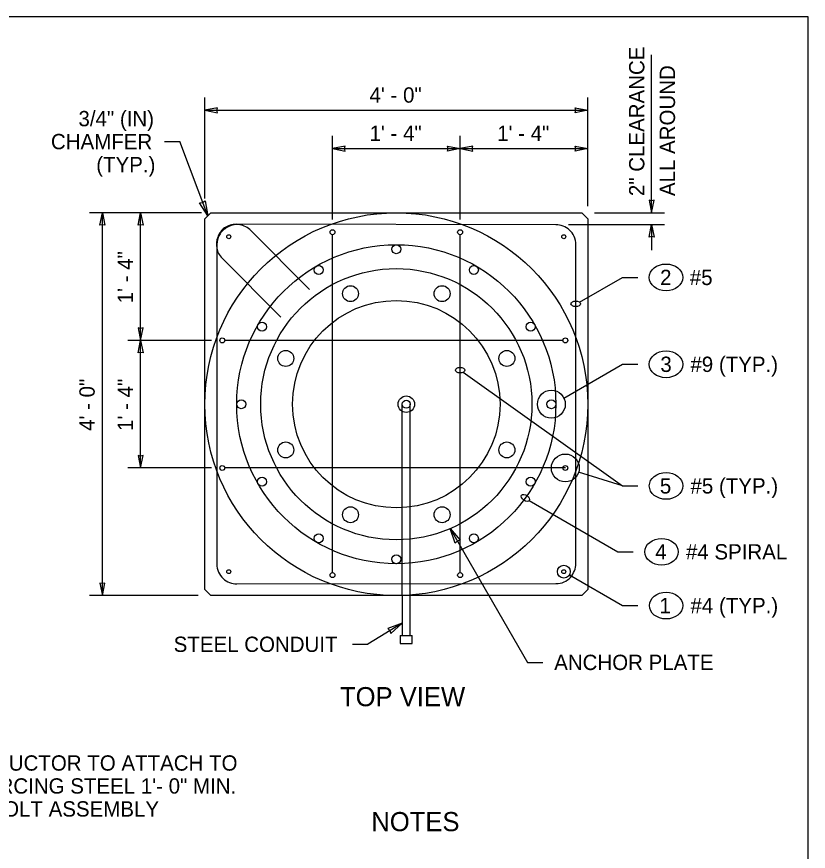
# Model space of a CAD drawing. Extents: x 99862 to 104211, y 98939 to 105076.
# Drawn here: x 102323 to 103150, y 101203 to 102075 of the extents above; entities that cross this region are included whole.
import ezdxf

# ---------------------------------------------------------------- set-up
doc = ezdxf.new("R2010")
doc.units = 0
for name, color, linetype in [('Level 10', 7, 'Continuous'), ('Level 15', 7, 'Continuous'), ('Level 2', 7, 'Continuous'), ('Level 20', 7, 'Continuous'), ('Level 6', 7, 'Continuous'), ('Level 60', 7, 'Continuous')]:
    doc.layers.add(name, color=color, linetype=linetype)

msp = doc.modelspace()

# ---------------------------------------------------------------- linework, layer by layer
at = {"layer": 'Level 10'}
for p, q in [((102886.32, 101857.61), (102552.49, 101858.08)), ((102629.08, 101790.09), (102567.69, 101851.48)), ((102652.96, 101494.06), (102652.96, 101847.19)), ((102786.29, 101494.06), (102786.29, 101847.19)), ((102532.12, 101836.75), (102532.12, 101503.2)), ((102907.12, 101503.4), (102907.12, 101836.78)), ((102537.73, 101822.51), (102599.1, 101761.14)), ((102893.58, 101736.76), (102540.46, 101736.76)), ((102896.19, 101603.43), (102540.46, 101603.43)), ((102552.97, 101482.36), (102886.3, 101482.57))]:
    msp.add_line(p, q, dxfattribs=at)
for centre, radius in [((102544.62, 101845.09), 2.08), ((102652.96, 101849.79), 2.6), ((102786.29, 101849.79), 2.6), ((102894.62, 101845.09), 2.08), ((102719.62, 101670.09), 166.67), ((102719.62, 101832.06), 4.7), ((102719.62, 101670.09), 141.67), ((102638.64, 101810.36), 4.7), ((102800.61, 101810.36), 4.7), ((102671.79, 101785.58), 8.33), ((102767.46, 101785.58), 8.33), ((102719.62, 101670.09), 108.33), ((102579.36, 101751.08), 4.7), ((102859.89, 101751.08), 4.7), ((102537.85, 101736.76), 2.6), ((102896.19, 101736.76), 2.6), ((102604.14, 101717.93), 8.33), ((102835.11, 101717.93), 8.33), ((102557.66, 101670.09), 4.7), ((102881.59, 101670.09), 4.7), ((102604.14, 101622.26), 8.33), ((102835.11, 101622.26), 8.33), ((102537.85, 101603.43), 2.6), ((102896.19, 101603.43), 2.6), ((102579.36, 101589.11), 4.7), ((102859.89, 101589.11), 4.7), ((102671.79, 101554.61), 8.33), ((102767.46, 101554.61), 8.33), ((102638.64, 101529.83), 4.7), ((102800.61, 101529.83), 4.7), ((102719.62, 101508.13), 4.7), ((102544.62, 101495.09), 2.08), ((102652.96, 101491.46), 2.6), ((102786.29, 101491.46), 2.6), ((102894.62, 101495.09), 2.08)]:
    msp.add_circle(centre, radius, dxfattribs=at)
for points in [[(102552.49, 101858.08), (102548.08, 101858.08), (102539.04, 101855.2), (102532.06, 101845.12), (102531.09, 101832.73), (102534.26, 101825.99), (102537.73, 101822.51)], [(102567.69, 101851.48), (102564.57, 101854.6), (102556.13, 101858.94), (102544.07, 101856.73), (102534.64, 101848.65), (102532.12, 101841.66), (102532.12, 101836.75)], [(102907.12, 101836.79), (102907.14, 101843.06), (102902.02, 101853.68), (102891.25, 101857.61), (102886.32, 101857.61)], [(102532.12, 101503.19), (102532.11, 101496.91), (102537.23, 101486.28), (102548.02, 101482.36), (102552.97, 101482.36)], [(102886.31, 101482.57), (102892.59, 101482.56), (102903.2, 101487.69), (102907.12, 101498.47), (102907.12, 101503.4)]]:
    msp.add_open_spline(points, degree=3, dxfattribs=at)
at = {"layer": 'Level 15'}
for p, q in [((102986.29, 101870.09), (102986.29, 102035.24)), ((102519.62, 101885.01), (102519.62, 101990.51)), ((102919.62, 101877.18), (102919.62, 101990.51)), ((102519.62, 101977.18), (102919.62, 101977.18)), ((102477.63, 101944.49), (102493.63, 101944.49)), ((102522.75, 101866.97), (102493.63, 101944.49)), ((102652.96, 101863.13), (102652.96, 101950.51)), ((102786.29, 101863.13), (102786.29, 101950.51)), ((102652.96, 101937.18), (102786.29, 101937.18)), ((102786.29, 101937.18), (102919.62, 101937.18)), ((102516.28, 101870.09), (102399.21, 101870.09)), ((102412.54, 101470.09), (102412.54, 101870.09)), ((102452.54, 101736.76), (102452.54, 101870.09)), ((102926.71, 101870.09), (102999.62, 101870.09)), ((102899.61, 101857.82), (102999.62, 101857.82)), ((102986.29, 101857.82), (102986.29, 101831.15)), ((102911.09, 101776.72), (102955.85, 101802.57)), ((102955.85, 101802.57), (102971.85, 101802.57)), ((102526.59, 101736.76), (102439.21, 101736.76)), ((102452.54, 101603.43), (102452.54, 101736.76)), ((102894.71, 101676.46), (102955.85, 101711.77)), ((102955.85, 101711.77), (102971.85, 101711.77)), ((102789.44, 101703.39), (102955.93, 101584.73)), ((102526.59, 101603.43), (102439.21, 101603.43)), ((102955.93, 101584.73), (102910.1, 101599.07)), ((102955.93, 101584.73), (102971.93, 101584.73)), ((102858.57, 101569.28), (102951.17, 101515.82)), ((102775.85, 101540.06), (102856.54, 101400.31)), ((102951.17, 101515.82), (102967.17, 101515.82)), ((102900.46, 101491.72), (102955.96, 101459.68)), ((102512.54, 101470.09), (102399.21, 101470.09)), ((102955.96, 101459.68), (102971.96, 101459.68)), ((102725.87, 101441.16), (102689.85, 101419.2)), ((102673.85, 101419.2), (102689.85, 101419.2)), ((102856.54, 101400.31), (102872.54, 101400.31))]:
    msp.add_line(p, q, dxfattribs=at)
for points in [[(102519.62, 101977.18), (102532.73, 101974.61), (102532.12, 101977.18), (102532.73, 101979.75)], [(102919.62, 101977.18), (102906.52, 101974.61), (102907.13, 101977.18), (102906.52, 101979.75)], [(102652.96, 101937.18), (102666.06, 101934.61), (102665.45, 101937.18), (102666.06, 101939.75)], [(102786.29, 101937.18), (102773.19, 101934.61), (102773.79, 101937.18), (102773.19, 101939.75)], [(102786.29, 101937.18), (102799.39, 101934.61), (102798.79, 101937.18), (102799.39, 101939.75)], [(102919.62, 101937.18), (102906.52, 101934.61), (102907.13, 101937.18), (102906.52, 101939.75)], [(102522.75, 101866.97), (102514.2, 101880.52), (102517.34, 101880.96), (102519.96, 101882.75)], [(102986.29, 101870.09), (102988.86, 101883.2), (102986.29, 101882.59), (102983.72, 101883.2)], [(102412.54, 101870.09), (102415.11, 101856.99), (102412.54, 101857.59), (102409.97, 101856.99)], [(102452.54, 101870.09), (102455.11, 101856.99), (102452.54, 101857.59), (102449.97, 101856.99)], [(102986.29, 101857.82), (102988.86, 101844.72), (102986.29, 101845.32), (102983.72, 101844.72)], [(102452.54, 101736.76), (102455.11, 101749.86), (102452.54, 101749.26), (102449.97, 101749.86)], [(102452.54, 101736.76), (102455.11, 101723.65), (102452.54, 101724.26), (102449.97, 101723.65)], [(102452.54, 101603.43), (102455.11, 101616.53), (102452.54, 101615.92), (102449.97, 101616.53)], [(102775.86, 101540.07), (102786.36, 101527.96), (102783.32, 101527.06), (102781.01, 101524.89)], [(102412.54, 101470.09), (102415.11, 101483.2), (102412.54, 101482.59), (102409.97, 101483.2)], [(102725.87, 101441.16), (102710.79, 101435.76), (102712.99, 101433.49), (102713.94, 101430.46)]]:
    msp.add_lwpolyline(points, close=True, dxfattribs=at)
msp.add_circle((102894.62, 101495.09), 6.74, dxfattribs=at)
for centre, major_axis in [((102907.1, 101774.98), (-5, 0)), ((102786.29, 101705.63), (-5, 0)), ((102854.48, 101572.16), (-4.09, 2.87))]:
    msp.add_ellipse(centre, major_axis=major_axis, ratio=0.57735, dxfattribs=at)
at = {"layer": 'Level 2'}
for p, q in [((102525.87, 101870.09), (102519.62, 101863.84)), ((102525.87, 101870.09), (102913.37, 101870.09)), ((102913.37, 101870.09), (102919.62, 101863.84)), ((102519.62, 101476.34), (102519.62, 101863.84)), ((102919.62, 101863.84), (102919.62, 101476.34)), ((102519.62, 101476.34), (102525.87, 101470.09)), ((102913.37, 101470.09), (102919.62, 101476.34)), ((102913.37, 101470.09), (102525.87, 101470.09))]:
    msp.add_line(p, q, dxfattribs=at)
for centre, radius in [((102719.62, 101670.09), 200), ((102881.59, 101670.09), 14.58), ((102896.19, 101603.43), 14.58)]:
    msp.add_circle(centre, radius, dxfattribs=at)
at = {"layer": 'Level 20'}
for centre in [(103001.35, 101802.57), (103001.35, 101711.77), (103001.43, 101584.73), (102996.67, 101515.82), (103001.46, 101459.68)]:
    msp.add_ellipse(centre, major_axis=(-17.5, 0), ratio=0.8, dxfattribs=at)
at = {"layer": 'Level 6'}
for p, q in [((102725.87, 101470.09), (102725.87, 101670.09)), ((102734.21, 101470.09), (102734.21, 101670.09)), ((102725.87, 101470.09), (102725.87, 101428.43)), ((102734.21, 101428.43), (102734.21, 101470.09)), ((102723.79, 101428.43), (102723.79, 101420.09)), ((102723.79, 101428.43), (102736.29, 101428.43)), ((102736.29, 101420.09), (102736.29, 101428.43)), ((102723.79, 101420.09), (102736.29, 101420.09))]:
    msp.add_line(p, q, dxfattribs=at)
for radius in [8.61, 4.17]:
    msp.add_circle((102730.04, 101670.09), radius, dxfattribs=at)
at = {"layer": 'Level 60'}
for p, q in [((103150, 102075), (100000, 102075)), ((103150, 100000), (103150, 102075))]:
    msp.add_line(p, q, dxfattribs=at)

# ---------------------------------------------------------------- texts
at = {"layer": 'Level 20'}
for s, p in [('2" CLEARANCE', (102978.78, 101887.55)), ('ALL AROUND', (103010.78, 101887.55)), ('1\' - 4"', (102444.54, 101775.49)), ('4\' - 0"', (102404.54, 101642.16)), ('1\' - 4"', (102444.54, 101642.16))]:
    msp.add_text(s, height=16, rotation=90, dxfattribs=at).set_placement(p)
for s, height, p in [('4\' - 0"', 16, (102691.69, 101985.18)), ('3/4" (IN) ', 16, (102387.58, 101960.49)), ('1\' - 4"', 16, (102691.69, 101945.18)), ('1\' - 4"', 16, (102825.02, 101945.18)), ('CHAMFER', 16, (102358.85, 101936.49)), ('(TYP.)', 16, (102406.17, 101912.49)), ('2', 16, (102995.17, 101794.57)), ('#5', 16, (103026.21, 101794.57)), ('3', 16, (102995.45, 101703.77)), ('#9 (TYP.)', 16, (103026.85, 101703.77)), ('#5 (TYP.)', 16, (103026.93, 101576.73)), ('5', 16, (102994.94, 101576.73)), ('4', 16, (102990.08, 101507.82)), ('#4 SPIRAL', 16, (103022.17, 101507.82)), ('1', 16, (102994.51, 101451.68)), ('#4 (TYP.)', 16, (103026.96, 101451.68)), ('STEEL CONDUIT', 16, (102487.07, 101411.2)), ('ANCHOR PLATE', 16, (102884.54, 101392.31)), ('TOP VIEW', 20, (102660.78, 101354.47)), ('GROUNDING CONDUCTOR TO ATTACH TO ', 16, (102112.74, 101287.16)), ('VERTICAL REINFORCING STEEL 1\'- 0" MIN. ', 16, (102112.74, 101263.16)), ('BELOW ANCHOR BOLT ASSEMBLY', 16, (102112.74, 101239.16)), ('NOTES', 20, (102693.51, 101223.92))]:
    msp.add_text(s, height=height, dxfattribs=at).set_placement(p)

doc.saveas('drawing.dxf')
